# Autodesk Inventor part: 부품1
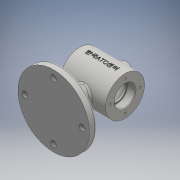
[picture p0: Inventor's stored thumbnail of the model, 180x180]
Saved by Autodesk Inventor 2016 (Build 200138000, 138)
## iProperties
Created: 2018-12
Part Number: 부품1
Material: Generic
Document SubType Name: Modeling
Designer: Administrator
Density: 1 g/cm^3
Appearance: Default
Author: Administrator
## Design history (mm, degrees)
sketch "스케치1"
  geometry: C1 r 30 at (0, 0); 1 further point
  constraints: 1 centre point, 1 coincident
  dimensions: "d0" = 60 diameter of C1
extrude "돌출1" new body sketch "스케치1" stored distance "d1" = 70; taper "d2" = 0 deg
sketch "스케치2"
  geometry: L1 (-35, 30)-(-35, -30) reference; L2 (-35, 16)-(-23, 16); L3 (-23, 16)-(-23, 14.3); L4 (-22.7, 14)-(-20, 14); L5 (-20, 14)-(-20, 22); L6 (-17, 25)-(17, 25); L7 (20, 22)-(20, 14); L8 (20, 14)-(22.7, 14); L9 (23, 14.3)-(23, 16); L10 (23, 16)-(35, 16); L11 (-35, 16)-(-35, 0); L12 (35, -30)-(35, 30) reference; L13 (35, 0)-(-35, 0); L14 (35, 16)-(35, 0); A1 r 3 centre (-17, 22) between (-17, 25) and (-20, 22); A2 r 3 centre (17, 22) between (20, 22) and (17, 25); A3 r 0.3 centre (-22.7, 14.3) between (-23, 14.3) and (-22.7, 14); A4 r 0.3 centre (22.7, 14.3) between (22.7, 14) and (23, 14.3); 5 further points
  constraints: 24 end point, 9 point on line, 8 point on circle, 8 tangent, 6 perpendicular, 4 centre point, 3 horizontal, 2 midpoint, 1 collinear, 1 equal radius, 1 vertical
  dimensions: "d3" = 12 distance of L2.start L2.end; "d4" = 32 diameter of L2 L13; "d5" = 3 distance of point (-23, 14) L4.end; "d6" = 28 diameter of L4 L13; "d7" = 40 distance of point (-20, 25) point (20, 25); "d8" = 50 diameter of L6 L13; "d9" = 3 distance of L7.end point (23, 14); "d10" = 28 diameter of L8 L13; "d11" = 32 diameter of L10 L13; "d12" = 3 radius of A1; "d13" = 0.3 radius of A3; "d28" = 0.3 radius of A4
revolve "회전1" sketch "스케치2" stored, may be unused: angle "d14" = 90 deg
chamfer "모따기1" distance "d15" = 1; stored, may be unused: second distance "d16" = 2, angle "d17" = 45 deg
node "작업 평면1"
sketch "스케치3"
  geometry: C1 r 10 at (0, 0); 1 further point
  constraints: 1 centre point, 1 coincident
  dimensions: "d19" = 20 diameter of C1
extrude "돌출2" join sketch "스케치3" stored distance "d20" = 70; taper "d21" = 0 deg
sketch "스케치4"
  geometry: C1 r 5 at (0, 0); 1 further point
  constraints: 1 centre point, 1 coincident
  dimensions: "d22" = 10 diameter of C1
extrude "돌출3" cut sketch "스케치4" stored distance "d23" = 70; taper "d24" = 0 deg; dims "d3" = 12, "d4" = 32, "d5" = 3, "d6" = 28, "d7" = 40, "d8" = 50, "d9" = 3, "d10" = 28, "d11" = 32, "d12" = 3, "d13" = 0.3, "d28" = 0.3
chamfer "모따기2" distance "d25" = 1; stored, may be unused: second distance "d26" = 2, angle "d27" = 45 deg
sketch "스케치5"
  geometry: L1 (0, 0)-(-75, 0); L2 (-75, -55)-(-75, 55); L3 (-75, -55)-(-64, -55); L4 (-64, -55)-(-52.478, -12); L5 (-52.478, -12)-(-52.478, 0); L6 (-75, 0)-(-52.478, 0)
  constraints: 12 end point, 2 coincident, 2 horizontal, 1 collinear, 1 midpoint, 1 perpendicular, 1 point on line, 1 vertical
  dimensions: "d29" = 75 distance of L1.start L1.end; "d30" = 110 distance of L2.start L2.end; "d31" = 11 distance of L2.start L3.end; "d34" = 75 deg angle of L3 L4; "d35" = 12 distance of L4.end L5.end
revolve "회전2" sketch "스케치5" stored, may be unused: angle "d36" = 90 deg
sketch "스케치6"
  geometry: C1 r 12 at (0, 0); 1 further point
  constraints: 1 centre point, 1 coincident
  dimensions: "d37" = 24 diameter of C1
extrude "돌출4" join sketch "스케치6" stored distance "d38" = 70; taper "d39" = 0 deg
fillet "모깎기1" dims "d40" = 3
sketch "스케치7"
  geometry: C1 r 5 at (0, 0) reference; C2 r 4.5 at (-44, 0); C3 r 4.5 at (0, 44); C4 r 4.5 at (44, 0); C5 r 4.5 at (0, -44); A1 r 44 centre (0, 0) between (-44, 0) and (0, 44); 1 further point
  constraints: 5 centre point, 4 point on circle, 1 coincident
  dimensions: "d41" = 88 diameter of A1; "d42" = 9 diameter of C2; "d43" = 9 diameter of C3; "d44" = 9 diameter of C4; "d45" = 9 diameter of C5
extrude "돌출5" cut sketch "스케치7" distance "d46" = 10; taper "d47" = 0 deg
sketch "스케치8"
  geometry: C1 r 5 at (0, -44) reference; C2 r 7 at (-44, -44); C3 r 7 at (0, 0); C4 r 7 at (44, -44); C5 r 7 at (0, -88); A1 r 44 centre (0, -44) between (-44, -44) and (0, 0); 1 further point
  constraints: 5 centre point, 4 point on circle, 1 coincident
  dimensions: "d48" = 88 diameter of A1; "d49" = 14 diameter of C2; "d50" = 14 diameter of C3; "d51" = 14 diameter of C4; "d52" = 14 diameter of C5
extrude "돌출6" cut sketch "스케치8" distance "d53" = 10; taper "d54" = 0 deg
sketch "스케치9"
  geometry: C1 r 16 at (0, 0) reference; A1 r 23 centre (0, 0) between (-23, 0) and (0, 23); 3 further points
  constraints: 4 point on circle, 1 centre point, 1 coincident
  dimensions: "d55" = 46 diameter of A1
hole "구멍1" sketch "스케치9" at (-23, 0), (0, 23), (0, -23), (23, 0) diameter "d56" = 3.242; stored, may be unused: countersink angle "d60" = 90 deg, drill point angle "d62" = 118 deg; dims "d57" = 8, "d58" = 14, "d59" = 2, "d61" = 10
fillet "모깎기2" dims "d63" = 3
node "작업 평면2"
sketch "스케치10"
  geometry: L1 (-35, 30)-(-35, -30) reference; 2 further points
  constraints: 1 other
  dimensions: "d65" = 35 distance from line of L1 point (0, 0); "d66" = 30 vertical distance of L1.start point (0, 0)
feature "엠보싱1" sketch "스케치10" dims "d3" = 12, "d4" = 32, "d5" = 3, "d6" = 28, "d7" = 40, "d8" = 50, "d9" = 3, "d10" = 28, "d11" = 32, "d12" = 3, "d13" = 0.3, "d28" = 0.3, "d67" = 0.5, "d68" = 0
node "솔리드1"
mirror "대칭1"
other parameters: "d18" = 37, "d32" = 75 deg
